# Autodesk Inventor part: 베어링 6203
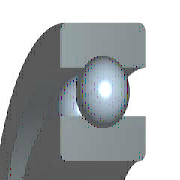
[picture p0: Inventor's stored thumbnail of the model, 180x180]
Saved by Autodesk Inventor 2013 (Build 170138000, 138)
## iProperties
IsCustomPart: 0
Created: 2016-04
Part Number: 베어링 6203
Material: 강철, 연강
Description: 깊은 그루브 볼 베어링
Document SubType Name: Modeling
Standard: KS B 2023
Designer: mdu
Standards Organization: KS
Language: ko-KR
Size Designation: 6203 - 17 x 40 x 12
Categories: <MemberInstance><Categories><Category DisplayName="샤프트 부품" InternalName="7f7aeb1f-a693-4053-b835-cee3144e0d98" Mnemonic="SHFT"><Category DisplayName="베어링" Inter
Density: 7.86 g/cm^3
Mass: 64.9809 g
Surface Area: 64.3582 cm^2
Volume: 8.26729 cm^3
Author: mdu
Revision Number: 1
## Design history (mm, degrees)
sketch "스케치" dims "d0" = 5.98 (= -0.26 x WD + 0.26 x BD)
  geometry: L1 (3.01, 14.25)-(8.99, 14.25); L2 (6, 14.25)-(6, 11.26); L3 (6, 14.25)-(6, 17.24); L4 (3.778, 12.249)-(0, 12.249); L5 (0, 8.5)-(12, 8.5); L6 (3.778, 16.251)-(0, 16.251); L7 (0, 20)-(12, 20); L8 (12, 8.5)-(12, 12.249); L9 (8.222, 12.249)-(12, 12.249); L10 (8.222, 16.251)-(12, 16.251); L11 (12, 20)-(12, 16.251); L12 (-1.4, 0)-(8.4, 0) reference; L13 (0, -0.3)-(0, 5.3) reference
  constraints: 22 end point, 4 point on line, 2 collinear, 2 perpendicular, 2 symmetric about line, 1 midpoint, 1 parallel, 14 other
  dimensions: "d9" = 17 diameter of L5 L12 (= WD); "d11" = 40 diameter of L7 L12 (= BD); "d12" = 12 distance between parallel lines of L8 L13 (= KB); "d13" = 24.498 diameter of L9 L12 (= 0.326 x BD + 0.674 x WD)
revolve "본체" stored, may be unused: angle "d6" = 90 deg
revolve "볼" stored, may be unused: angle "d7" = 90 deg
pattern_circular "IDS_ARRAYBALL[SIMPL:T]" dims angle "d3" = 360 deg
body "Solid1"
fillet "모깎기1" dims "d1" = 0.6 (= KRS)
other parameters: "WD" = 17 [user parameter; used in 5 equation terms], "BD" = 40 [user parameter; used in 5 equation terms], "KB" = 12 [user parameter; used in 1 equation term], "KRS" = 0.6 [user parameter; used in 1 equation term], "d4" = 0, "d5" = 0, "d8" = 0, "d14" = 0, "d15" = 0, "BBA" = 0 [user parameter], "BC0" = 4750000 [user parameter], "BC" = 9560000 [user parameter], "WR" = 8.5 (= 0.5 x WD) [user parameter]
